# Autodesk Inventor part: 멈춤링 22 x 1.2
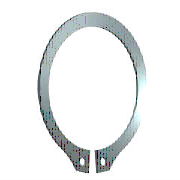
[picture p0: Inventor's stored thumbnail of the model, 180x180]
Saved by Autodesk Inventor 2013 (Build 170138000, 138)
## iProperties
IsCustomPart: 0
Created: 2021-07
Part Number: 멈춤링 22 x 1.2
Material: 강철, 연강
Description: 리테이닝 링(C형)
Document SubType Name: Modeling
Standard: KS B 1336
Designer: mdu
Standards Organization: KS
Language: ko-KR
Size Designation: 22 x 1.2
Categories: <MemberInstance><Categories><Category DisplayName="샤프트 부품" InternalName="7f7aeb1f-a693-4053-b835-cee3144e0d98" Mnemonic="SHFT"><Category DisplayName="써클립" Inter
Density: 7.86 g/cm^3
Mass: 1.82859 g
Surface Area: 5.91219 cm^2
Volume: 0.232645 cm^3
Author: mdu
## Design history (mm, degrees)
sketch "스케치1"
  geometry: L1 (-6, 0)-(6, 0) reference; L2 (0, 20.189)-(0, -80.536) reference; L3 (-48.09, 0)-(48.09, 0) reference; L4 (-0.5, -21.488)-(-0.5, -25.588); L5 (-0.5, -6.54)-(-0.5, -13.29); L6 (-2.795, 2.7)-(3.672, 2.7); L7 (0.5, -6.54)-(0.5, -13.29); L8 (0.5, -21.488)-(0.5, -25.588); C1 r 1 at (-2, -23.437); C2 r 1 at (2, -23.437); A1 r 10.5 centre (0, -11) between (0.5, -21.488) and (-0.5, -21.488); A2 r 13.025 centre (0, -10.325) between (5.149, -22.289) and (-5.149, -22.289); A3 r 14.597 centre (0, -11) between (-2.318, -25.411) and (-0.5, -25.588); A4 r 2 centre (-2, -23.437) between (-3.97, -23.781) and (-2.318, -25.411); A5 r 2 centre (-5.94, -24.126) between (-3.97, -23.781) and (-5.149, -22.289); A6 r 2 centre (5.94, -24.126) between (5.149, -22.289) and (3.97, -23.781); A7 r 2 centre (2, -23.437) between (2.318, -25.411) and (3.97, -23.781); A8 r 14.597 centre (0, -11) between (0.5, -25.588) and (2.318, -25.411)
  constraints: 16 point on circle, 12 end point, 10 centre point, 9 symmetric about line, 5 point on line, 4 tangent, 3 coincident, 2 horizontal, 1 perpendicular, 1 vertical, 5 other
  dimensions: "d0" = 21 diameter of A1 (= ND); "d1" = 4.1 distance of L4.end L4.start (= SRB2); "d6" = 0.5 distance between parallel lines of L2 L5 (= 0.25 x SD5); "d7" = 2.7 distance between parallel lines of L6 L3 (= SRB1); "d8" = 0.675 distance of A1.centre A2.centre (= 0.25 x SRB1); "d9" = 2 radius of A4 (= SD5); "d10" = 2 radius of A5 (= SD5); "d11" = 1.5 distance from line of L4 A4.centre (= 0.75 x SD5); "d12" = 2 diameter of C1 (= SD5); "d13" = 2 diameter of C2 (= SD5); "d14" = 11 distance from line of A1.centre L1 (= 0.5 x WD)
extrude "본체" new body sketch "스케치1" distance "d2" = 1.2 (= SD); taper "d3" = 0 deg
workaxis "Work Axis1"
workplane "Work Plane1"
body "Solid1"
other parameters: "WD" = 22 (= WDMIN) [user parameter; used in 1 equation term], "SD" = 1.2 [user parameter; used in 1 equation term], "SRB1" = 2.7 [user parameter; used in 2 equation terms], "ND" = 21 [user parameter; used in 1 equation term], "SRB2" = 4.1 [user parameter; used in 1 equation term], "SD5" = 2 [user parameter; used in 6 equation terms], "d15" = 0, "d16" = 0, "d17" = 0, "d41" = 0, "d42" = 0, "WDMIN" = 22 [user parameter; used in 1 equation term], "SD3" = 20.5 [user parameter], "WDMAX" = 24 [user parameter]
